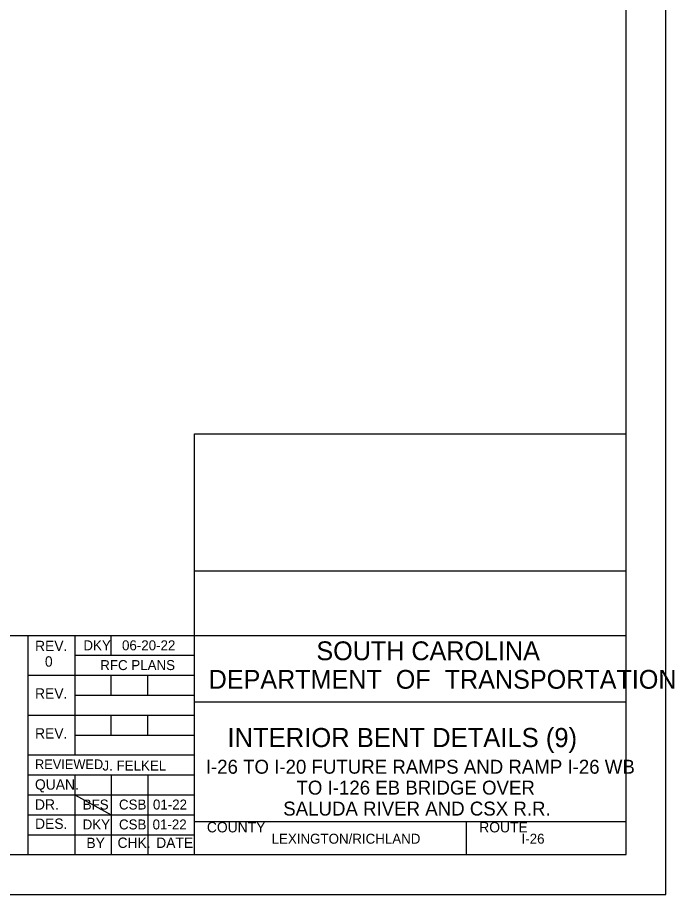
# Model space of a CAD drawing. Extents: x -133.1 to -97, y -110.1 to -88.1.
# Drawn here: x -105.28 to -97.03, y -110.1 to -99.1 of the extents above; entities that cross this region are included whole.
import ezdxf

# ---------------------------------------------------------------- set-up
doc = ezdxf.new("R2010")
doc.units = 0
for name, color, linetype in [('BR_BORDER LINES', 7, 'Continuous'), ('BR_TEXT', 7, 'Continuous'), ('Level 31', 7, 'Continuous')]:
    doc.layers.add(name, color=color, linetype=linetype)

msp = doc.modelspace()

# ---------------------------------------------------------------- linework, layer by layer
at = {"layer": 'BR_BORDER LINES'}
for p, q in [((-97.642, -109.603), (-97.642, -88.603)), ((-103.058, -109.603), (-103.058, -104.326)), ((-103.058, -104.326), (-97.642, -104.326)), ((-103.058, -106.041), (-97.642, -106.041)), ((-110.507, -106.853), (-105.142, -106.853)), ((-105.142, -109.603), (-105.142, -106.853)), ((-105.142, -106.853), (-97.642, -106.853)), ((-104.559, -106.853), (-104.559, -108.353)), ((-104.1, -107.103), (-104.1, -106.853)), ((-104.559, -107.103), (-103.058, -107.103)), ((-105.142, -107.353), (-103.058, -107.353)), ((-104.1, -107.603), (-104.1, -107.353)), ((-103.642, -107.603), (-103.642, -107.353)), ((-104.559, -107.603), (-103.058, -107.603)), ((-103.058, -107.686), (-103.058, -107.686)), ((-103.058, -107.686), (-97.641, -107.686)), ((-105.142, -107.853), (-103.058, -107.853)), ((-104.1, -108.103), (-104.1, -107.853)), ((-103.642, -108.103), (-103.642, -107.853)), ((-104.559, -108.103), (-103.058, -108.103)), ((-105.142, -108.353), (-103.058, -108.353)), ((-105.142, -108.603), (-103.058, -108.603)), ((-104.559, -108.603), (-104.559, -109.603)), ((-104.1, -108.603), (-104.1, -109.603)), ((-103.642, -108.603), (-103.642, -109.603)), ((-105.142, -108.853), (-103.058, -108.853)), ((-105.142, -109.103), (-103.058, -109.103)), ((-103.058, -109.186), (-97.642, -109.186)), ((-102.961, -109.186), (-97.642, -109.186)), ((-99.642, -109.603), (-99.642, -109.186)), ((-105.142, -109.353), (-103.058, -109.353)), ((-131.308, -109.603), (-97.642, -109.603))]:
    msp.add_line(p, q, dxfattribs=at)
at = {"layer": 'Level 31'}
for p, q in [((-100.35, -108.126), (-100.35, -108.126)), ((-104.559, -108.853), (-104.1, -109.103))]:
    msp.add_line(p, q, dxfattribs=at)
msp.add_lwpolyline([(-133.141, -110.103), (-97.141, -110.103), (-97.141, -88.103), (-133.141, -88.103)], close=True, dxfattribs=at)

# ---------------------------------------------------------------- texts
at = {"layer": 'BR_TEXT'}
for s, height, p in [('REV.', 0.13, (-105.057, -107.05)), ('DKY', 0.125, (-104.45, -107.04)), ('06-20-22', 0.125, (-103.966, -107.04)), ('SOUTH CAROLINA', 0.23587, (-101.527, -107.164)), ('0', 0.13, (-104.933, -107.245)), ('RFC PLANS', 0.125, (-104.239, -107.288)), ('DEPARTMENT  OF  TRANSPORTATION', 0.23587, (-102.879, -107.522)), ('REV.', 0.13, (-105.057, -107.647)), ('REV.', 0.13, (-105.057, -108.147)), ('INTERIOR BENT DETAILS (9)', 0.24, (-102.643, -108.254)), ('REVIEWED', 0.12, (-105.058, -108.529)), ('J. FELKEL', 0.125, (-104.211, -108.548)), ('I-26 TO I-20 FUTURE RAMPS AND RAMP I-26 WB', 0.175, (-102.915, -108.588)), ('QUAN.', 0.13, (-105.058, -108.788)), ('TO I-126 EB BRIDGE OVER', 0.175, (-101.777, -108.85)), ('DR.', 0.13, (-105.058, -109.039)), ('BFS', 0.125, (-104.459, -109.037)), ('CSB', 0.125, (-104.004, -109.037)), ('01-22', 0.125, (-103.578, -109.037)), ('SALUDA RIVER AND CSX R.R.', 0.175, (-101.943, -109.113)), ('DES.', 0.13, (-105.057, -109.28)), ('DKY', 0.125, (-104.46, -109.287)), ('CSB', 0.125, (-104.004, -109.287)), ('01-22', 0.125, (-103.582, -109.287)), ('COUNTY', 0.13, (-102.901, -109.324)), ('ROUTE', 0.13, (-99.484, -109.324)), ('LEXINGTON/RICHLAND', 0.12499, (-102.089, -109.466)), ('I-26', 0.125, (-98.953, -109.466)), ('BY', 0.13, (-104.413, -109.521)), ('CHK.', 0.13, (-104.022, -109.519)), ('DATE', 0.13, (-103.537, -109.519))]:
    msp.add_text(s, height=height, dxfattribs=at).set_placement(p)

doc.saveas('drawing.dxf')
